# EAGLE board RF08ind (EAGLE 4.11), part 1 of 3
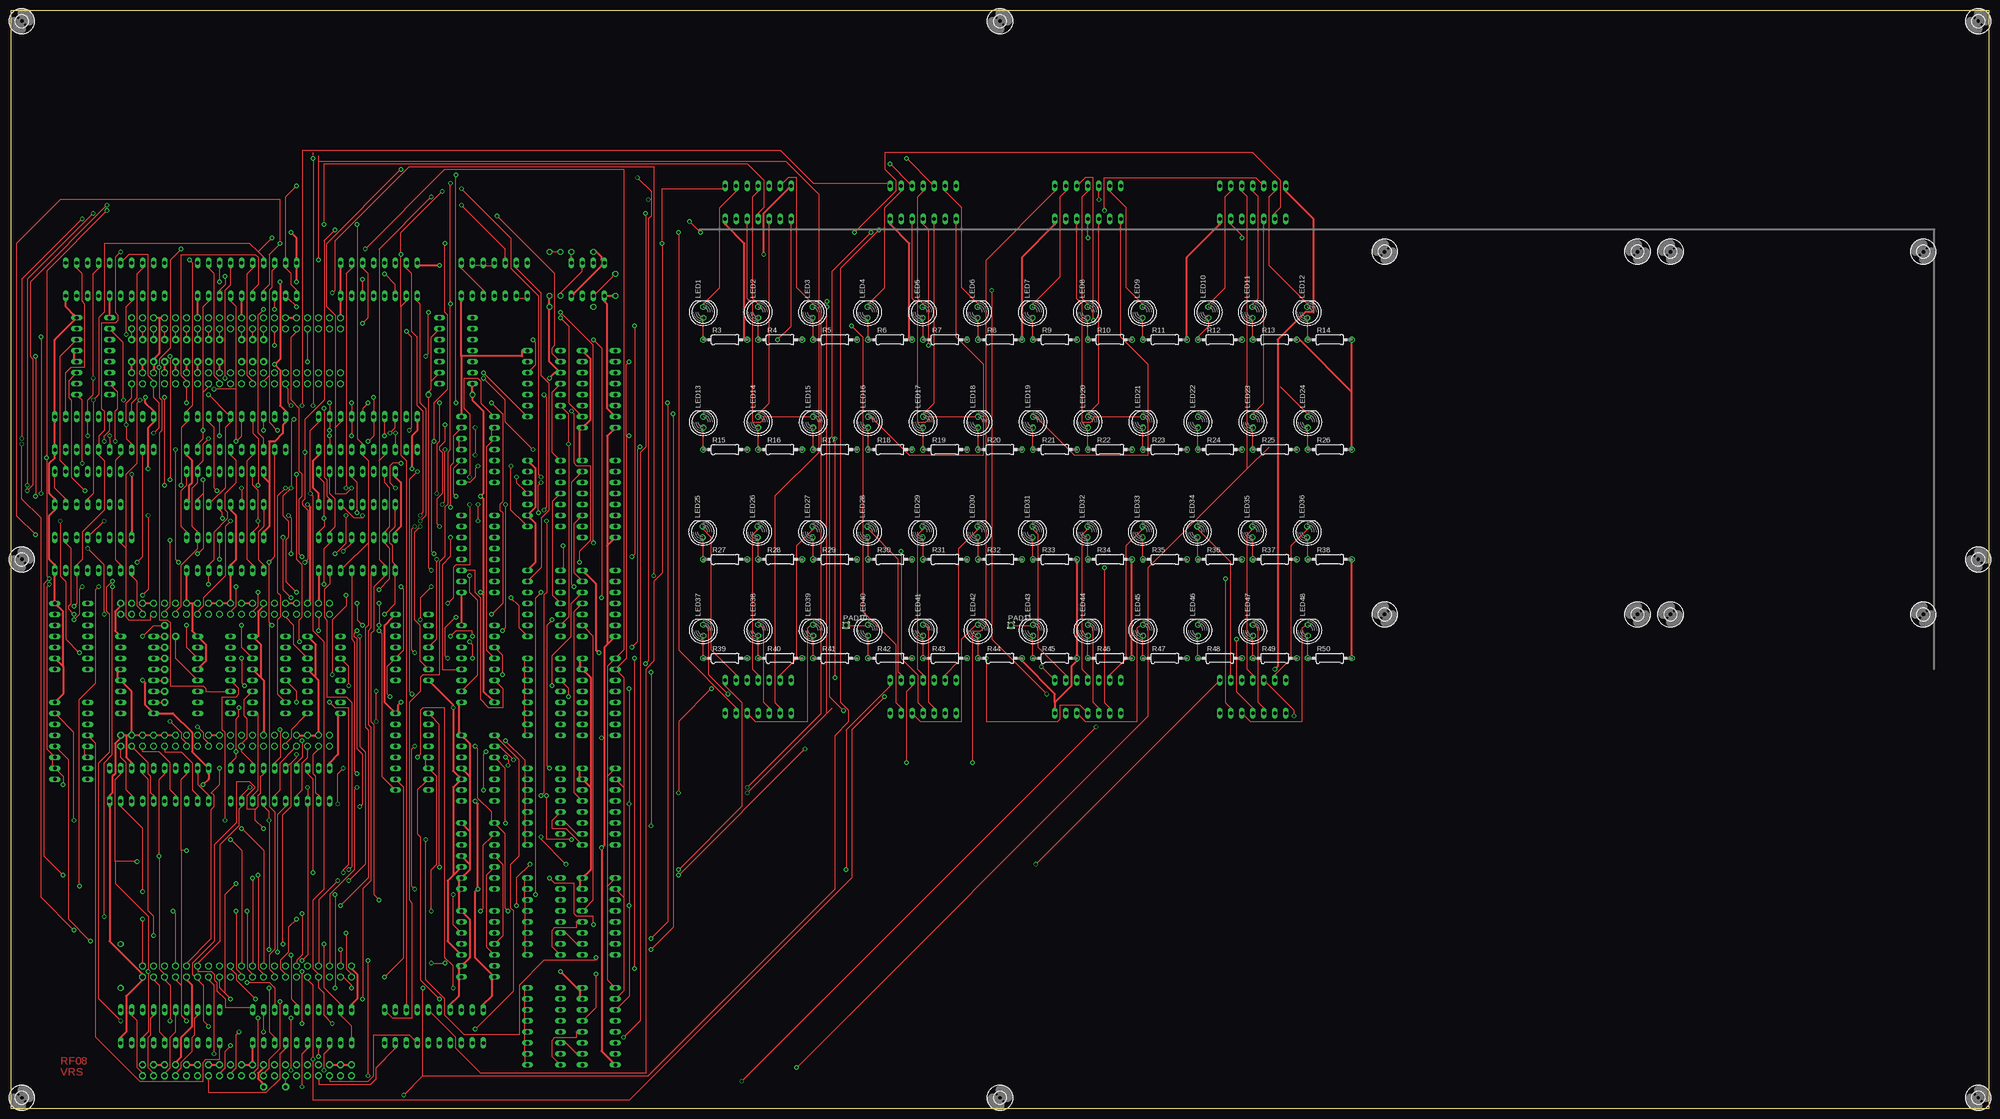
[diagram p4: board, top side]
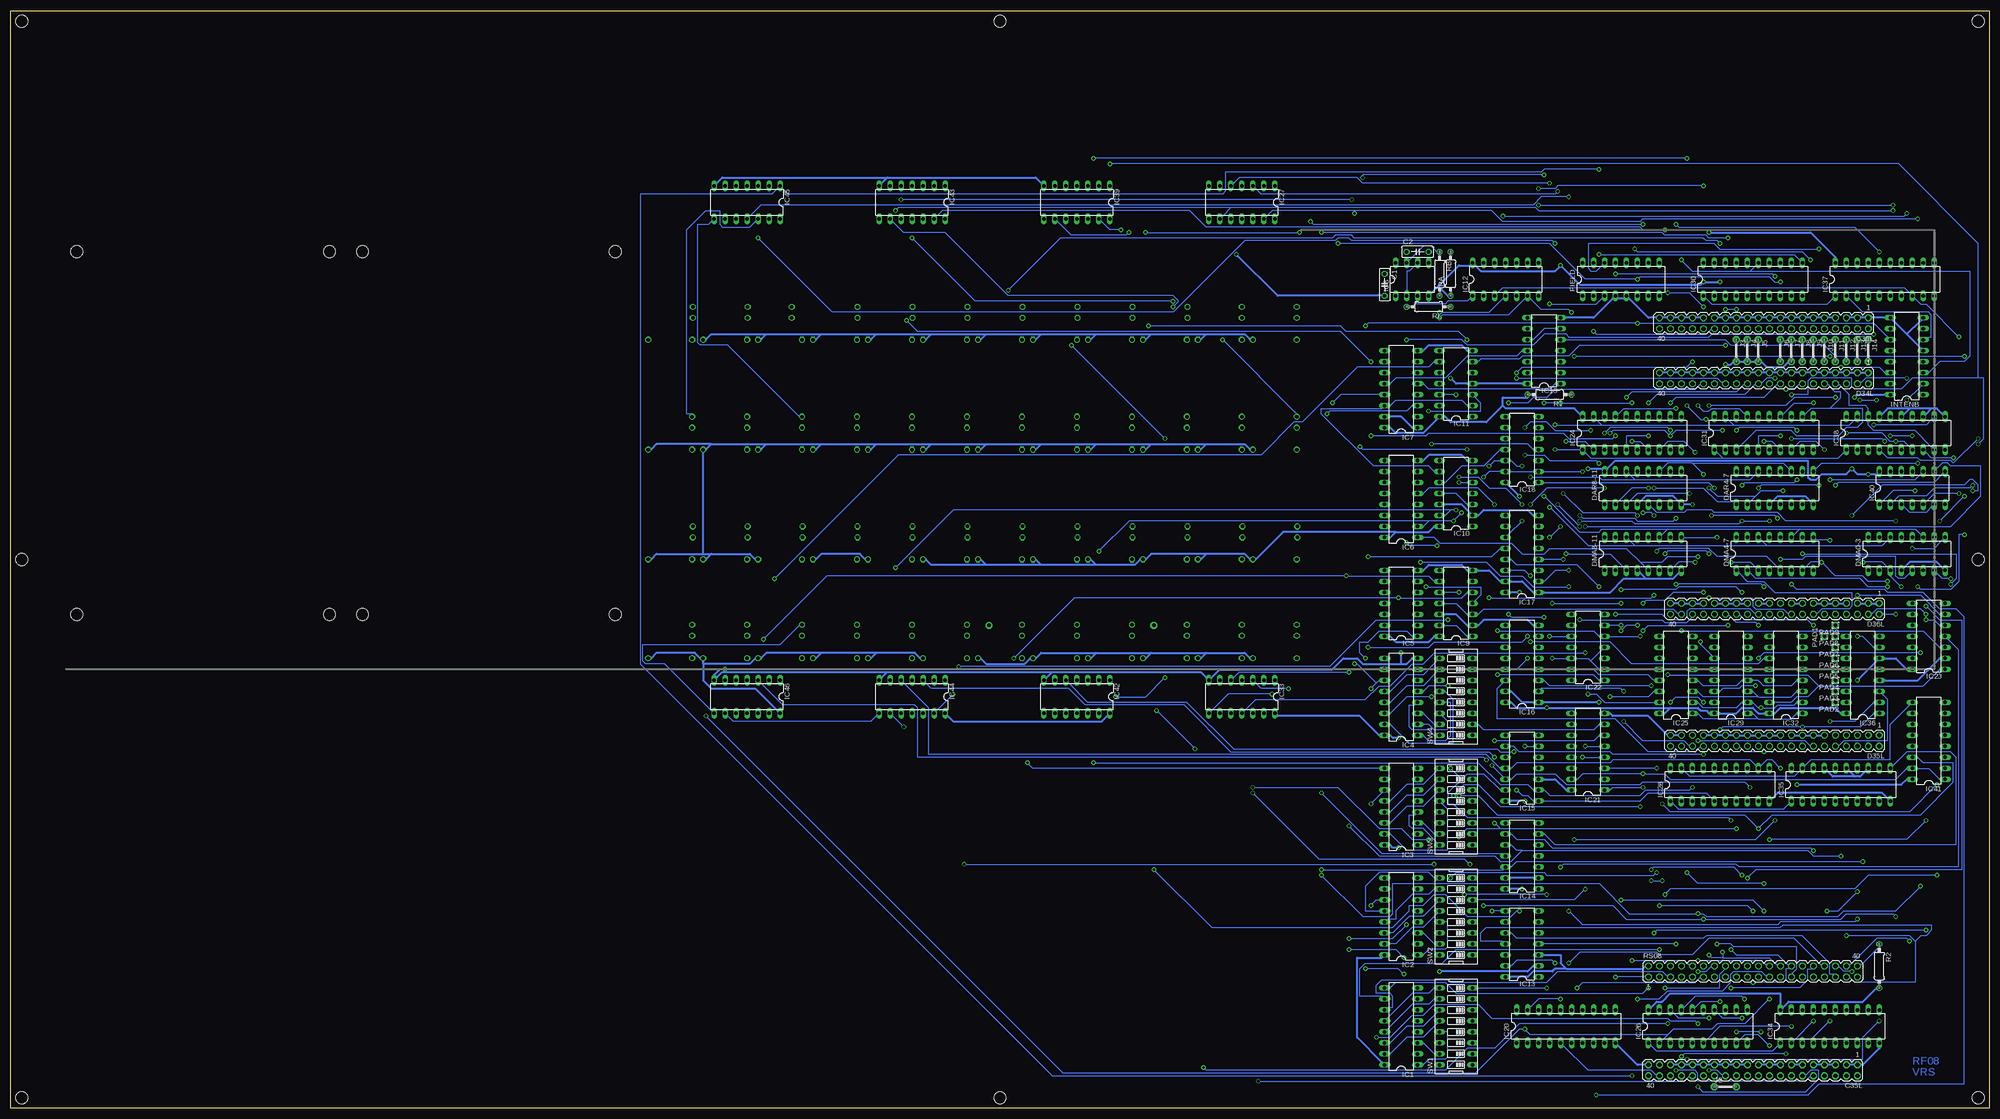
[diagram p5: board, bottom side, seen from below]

Size 457.18 x 253.67 mm. Coordinates in mm from the lower left corner, seen from the top.
Outline: 0,0 457.18,0 457.18,253.67 0,253.67 0,0
Copper layers (1*16): Top 0.035mm / dielectric 1.5mm / Bottom 0.035mm
Design rules "default": minimum track width 10mil, minimum drill 24mil, track to track 8mil, track to pad 8mil, pad to pad 8mil, via to via 8mil, smd to smd 8mil, copper to edge 40mil, drill to drill 8mil, minimum pad ring 10mil, minimum via ring 8mil, stop-mask expansion 4mil, vias tented up to drill 0mil, thermal gap 10mil
Net classes: 1 Power: width 0.508 mm

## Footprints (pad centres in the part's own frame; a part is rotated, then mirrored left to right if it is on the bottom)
C050-025X075 = drill 0.813 octagon: 1 -2.54,0; 2 2.54,0
MA20-2 = drill 1.016 octagon: 1 -24.13,-1.27; 2 -24.13,1.27; 3 -21.59,-1.27; 4 -21.59,1.27; 5 -19.05,-1.27; 6 -19.05,1.27; 7 -16.51,-1.27; 8 -16.51,1.27; 9 -13.97,-1.27; 10 -13.97,1.27; 11 -11.43,-1.27; 12 -11.43,1.27; 13 -8.89,-1.27; 14 -8.89,1.27; 15 -6.35,-1.27; 16 -6.35,1.27; 17 -3.81,-1.27; 18 -3.81,1.27; 19 -1.27,-1.27; 20 -1.27,1.27; 21 1.27,-1.27; 22 1.27,1.27; 23 3.81,-1.27; 24 3.81,1.27; 25 6.35,-1.27; 26 6.35,1.27; 27 8.89,-1.27; 28 8.89,1.27; 29 11.43,-1.27; 30 11.43,1.27; 31 13.97,-1.27; 32 13.97,1.27; 33 16.51,-1.27; 34 16.51,1.27; 35 19.05,-1.27; 36 19.05,1.27; 37 21.59,-1.27; 38 21.59,1.27; 39 24.13,-1.27; 40 24.13,1.27
DIL16 = drill 0.813 long: 1 -8.89,-3.81; 2 -6.35,-3.81; 3 -3.81,-3.81; 4 -1.27,-3.81; 5 1.27,-3.81; 6 3.81,-3.81; 7 6.35,-3.81; 8 8.89,-3.81; 9 8.89,3.81; 10 6.35,3.81; 11 3.81,3.81; 12 1.27,3.81; 13 -1.27,3.81; 14 -3.81,3.81; 15 -6.35,3.81; 16 -8.89,3.81
DIL14 = drill 0.813 long: 1 -7.62,-3.81; 2 -5.08,-3.81; 3 -2.54,-3.81; 4 0,-3.81; 5 2.54,-3.81; 6 5.08,-3.81; 7 7.62,-3.81; 8 7.62,3.81; 9 5.08,3.81; 10 2.54,3.81; 11 0,3.81; 12 -2.54,3.81; 13 -5.08,3.81; 14 -7.62,3.81
DIL08 = drill 0.813 long: 1 -3.81,-3.81; 2 -1.27,-3.81; 3 1.27,-3.81; 4 3.81,-3.81; 5 3.81,3.81; 6 1.27,3.81; 7 -1.27,3.81; 8 -3.81,3.81
DIL20 = drill 0.813 long: 1 -11.43,-3.81; 2 -8.89,-3.81; 3 -6.35,-3.81; 4 -3.81,-3.81; 5 -1.27,-3.81; 6 1.27,-3.81; 7 3.81,-3.81; 8 6.35,-3.81; 9 8.89,-3.81; 10 11.43,-3.81; 11 11.43,3.81; 12 8.89,3.81; 13 6.35,3.81; 14 3.81,3.81; 15 1.27,3.81; 16 -1.27,3.81; 17 -3.81,3.81; 18 -6.35,3.81; 19 -8.89,3.81; 20 -11.43,3.81
05 = drill 0.813 pad 1.6 octagon: 1 -2.54,0; 2 2.54,0
LED5MM = drill 0.813 octagon: A -1.27,0; K 1.27,0
1,6/0,8 = drill 0.813 pad 1.6 octagon: 1 0,0
0207/10 = drill 0.813 octagon: 1 -5.08,0; 2 5.08,0
EDG-08 = drill 0.813 long: 1 -8.89,-3.81; 2 -6.35,-3.81; 3 -3.81,-3.81; 4 -1.27,-3.81; 5 1.27,-3.81; 6 3.81,-3.81; 7 6.35,-3.81; 8 8.89,-3.81; 9 8.89,3.81; 10 6.35,3.81; 11 3.81,3.81; 12 1.27,3.81; 13 -1.27,3.81; 14 -3.81,3.81; 15 -6.35,3.81; 16 -8.89,3.81
2,8 = hole 2.8: 0,0

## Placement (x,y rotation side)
C1  .1uf  [C050-025X075]  139.69,190.34 270 bottom
C2  .1uf  [C050-025X075]  132.08,197.96 0 bottom
C35L  [MA20-2]  54.6,8.73 180 bottom
C36L  [MA20-2]  52.06,181.45 180 bottom
D34L  [MA20-2]  52.06,168.75 180 bottom
D35L  [MA20-2]  49.52,84.92 180 bottom
D36L  [MA20-2]  49.52,115.4 180 bottom
DAR4-7  74LS193N  [DIL16]  49.52,143.34 0 bottom
DAR8-11  74LS193N  [DIL16]  80.01,143.34 0 bottom
DMA0-3  74LS193N  [DIL16]  19.05,128.11 0 bottom
DMA4-7  74LS193N  [DIL16]  49.52,128.11 0 bottom
DMA8-11  74LS193N  [DIL16]  80.01,128.11 0 bottom
FIELD  74LS193N  [DIL16]  85.09,191.61 0 bottom
IC1  74LS151N  [DIL16]  135.88,18.89 90 bottom
IC2  74LS151N  [DIL16]  135.88,44.29 90 bottom
IC3  74LS151N  [DIL16]  135.88,69.68 90 bottom
IC4  74LS151N  [DIL16]  135.88,95.08 90 bottom
IC5  74LS20N  [DIL14]  135.88,116.67 90 bottom
IC6  74S139N  [DIL16]  135.88,140.81 90 bottom
IC7  74LS139N  [DIL16]  135.88,166.21 90 bottom
IC8  LM555N  [DIL08]  133.34,191.61 0 bottom
IC9  74S74N  [DIL14]  123.19,116.67 90 bottom
IC10  74S74N  [DIL14]  123.19,142.08 90 bottom
IC11  74S74N  [DIL14]  123.19,167.47 90 bottom
IC12  74LS00N  [DIL14]  111.76,191.61 0 bottom
IC13  74180N  [DIL14]  107.95,37.94 90 bottom
IC14  74180N  [DIL14]  107.95,58.26 90 bottom
IC15  74180N  [DIL14]  107.95,78.57 90 bottom
IC16  74S139N  [DIL16]  107.95,102.7 90 bottom
IC17  74S139N  [DIL16]  107.95,128.11 90 bottom
IC18  74LS00N  [DIL14]  107.95,152.24 90 bottom
IC19  7407N  [DIL14]  102.87,175.09 90 bottom
IC20  74S240N  [DIL20]  97.79,18.89 0 bottom
IC21  74LS139N  [DIL16]  92.7,82.38 90 bottom
IC22  7407N  [DIL14]  92.7,106.52 90 bottom
IC23  74S74N  [DIL14]  13.96,109.05 90 bottom
IC24  74S240N  [DIL20]  82.55,156.05 0 bottom
IC25  74S138N  [DIL16]  72.39,100.16 90 bottom
IC26  74S240N  [DIL20]  67.31,18.89 0 bottom
IC27  7404N  [DIL14]  172.72,209.39 180 bottom
IC28  74LS244N  [DIL20]  62.22,74.77 0 bottom
IC29  74S138N  [DIL16]  59.68,100.16 90 bottom
IC30  74S240N  [DIL20]  54.6,191.61 0 bottom
IC31  74S240N  [DIL20]  52.06,156.05 0 bottom
IC32  74S138N  [DIL16]  46.98,100.16 90 bottom
IC33  7404N  [DIL14]  172.72,95.08 180 bottom
IC34  74S240N  [DIL20]  36.82,18.89 0 bottom
IC35  74LS244N  [DIL20]  34.28,74.77 0 bottom
IC36  74S138N  [DIL16]  29.21,100.16 90 bottom
IC37  74S240N  [DIL20]  24.12,191.61 0 bottom
IC38  74S240N  [DIL20]  21.59,156.05 0 bottom
IC39  7404N  [DIL14]  210.81,209.39 180 bottom
IC40  74S03N  [DIL14]  17.78,143.34 0 bottom
IC41  74LS139N  [DIL16]  13.96,84.92 90 bottom
IC42  7404N  [DIL14]  210.81,95.08 180 bottom
IC43  7404N  [DIL14]  248.91,209.39 180 bottom
IC44  7404N  [DIL14]  248.91,95.08 180 bottom
IC45  7404N  [DIL14]  287.01,209.39 180 bottom
IC46  7404N  [DIL14]  287.01,95.08 180 bottom
INTENB  74LS193N  [DIL16]  19.05,173.83 90 bottom
J2  J5MM  [05]  60.95,4.92 0 bottom
J3  J5MM  [05]  58.41,175.09 270 bottom
J4  J5MM  [05]  55.88,175.09 270 bottom
J5  J5MM  [05]  53.34,175.09 270 bottom
J6  J5MM  [05]  48.25,175.09 270 bottom
J7  J5MM  [05]  45.71,175.09 270 bottom
J8  J5MM  [05]  43.17,175.09 270 bottom
J9  J5MM  [05]  40.63,175.09 270 bottom
J10  J5MM  [05]  38.09,175.09 270 bottom
J11  J5MM  [05]  35.55,175.09 270 bottom
J12  J5MM  [05]  33.02,175.09 270 bottom
J13  J5MM  [05]  30.48,175.09 270 bottom
J14  J5MM  [05]  27.94,175.09 270 bottom
LED1  [LED5MM]  160.02,183.99 90 top
LED2  [LED5MM]  172.72,183.99 90 top
LED3  [LED5MM]  185.29,183.99 90 top
LED4  [LED5MM]  197.99,183.99 90 top
LED5  [LED5MM]  210.69,183.99 90 top
LED6  [LED5MM]  223.39,183.99 90 top
LED7  [LED5MM]  236.09,183.99 90 top
LED8  [LED5MM]  248.79,183.99 90 top
LED9  [LED5MM]  261.49,183.99 90 top
LED10  [LED5MM]  276.73,183.99 90 top
LED11  [LED5MM]  286.89,183.99 90 top
LED12  [LED5MM]  299.59,183.99 90 top
LED13  [LED5MM]  160.02,158.59 90 top
LED14  [LED5MM]  172.72,158.59 90 top
LED15  [LED5MM]  185.41,158.59 90 top
LED16  [LED5MM]  198.12,158.59 90 top
LED17  [LED5MM]  210.81,158.59 90 top
LED18  [LED5MM]  223.52,158.59 90 top
LED19  [LED5MM]  236.22,158.59 90 top
LED20  [LED5MM]  248.91,158.59 90 top
LED21  [LED5MM]  261.62,158.59 90 top
LED22  [LED5MM]  274.31,158.59 90 top
LED23  [LED5MM]  287.01,158.59 90 top
LED24  [LED5MM]  299.72,158.59 90 top
LED25  [LED5MM]  159.89,133.19 90 top
LED26  [LED5MM]  172.59,133.19 90 top
LED27  [LED5MM]  185.29,133.19 90 top
LED28  [LED5MM]  197.99,133.19 90 top
LED29  [LED5MM]  210.69,133.19 90 top
LED30  [LED5MM]  223.39,133.19 90 top
LED31  [LED5MM]  236.09,133.19 90 top
LED32  [LED5MM]  248.79,133.19 90 top
LED33  [LED5MM]  261.49,133.19 90 top
LED34  [LED5MM]  274.19,133.19 90 top
LED35  [LED5MM]  286.89,133.19 90 top
LED36  [LED5MM]  299.59,133.19 90 top
LED37  [LED5MM]  160.02,110.45 90 top
LED38  [LED5MM]  172.72,110.45 90 top
LED39  [LED5MM]  185.41,110.45 90 top
LED40  [LED5MM]  198.12,110.45 90 top
LED41  [LED5MM]  210.81,110.45 90 top
LED42  [LED5MM]  223.52,110.45 90 top
LED43  [LED5MM]  236.22,110.45 90 top
LED44  [LED5MM]  248.91,110.45 90 top
LED45  [LED5MM]  261.62,110.45 90 top
LED46  [LED5MM]  274.31,110.45 90 top
LED47  [LED5MM]  287.01,110.45 90 top
LED48  [LED5MM]  299.72,110.45 90 top
PAD1  [1,6/0,8]  38.09,109.05 180 bottom
PAD2  [1,6/0,8]  35.55,93.81 180 bottom
PAD3  [1,6/0,8]  35.55,96.35 180 bottom
PAD4  [1,6/0,8]  35.55,98.89 180 bottom
PAD5  [1,6/0,8]  35.55,101.43 180 bottom
PAD6  [1,6/0,8]  35.55,103.97 180 bottom
PAD7  [1,6/0,8]  35.55,106.52 180 bottom
PAD8  [1,6/0,8]  35.55,109.05 180 bottom
PAD9  [1,6/0,8]  35.55,111.59 180 bottom
PAD10  [1,6/0,8]  193.03,111.59 0 top
PAD11  [1,6/0,8]  231.13,111.59 0 top
R1  5.1K  [0207/10]  101.59,164.94 180 bottom
R2  5.1K  [0207/10]  25.39,32.86 270 bottom
R3  330  [0207/10]  165.09,177.64 0 top
R4  330  [0207/10]  177.8,177.64 0 top
R5  330  [0207/10]  190.5,177.64 0 top
R6  330  [0207/10]  203.19,177.64 0 top
R7  330  [0207/10]  215.9,177.64 0 top
R8  330  [0207/10]  228.59,177.64 0 top
R9  330  [0207/10]  241.3,177.64 0 top
R10  330  [0207/10]  254,177.64 0 top
R11  330  [0207/10]  266.69,177.64 0 top
R12  330  [0207/10]  279.39,177.64 0 top
R13  330  [0207/10]  292.1,177.64 0 top
R14  330  [0207/10]  304.8,177.64 0 top
R15  330  [0207/10]  165.09,152.24 0 top
R16  330  [0207/10]  177.8,152.24 0 top
R17  330  [0207/10]  190.5,152.24 0 top
R18  330  [0207/10]  203.19,152.24 0 top
R19  330  [0207/10]  215.9,152.24 0 top
R20  330  [0207/10]  228.59,152.24 0 top
R21  330  [0207/10]  241.3,152.24 0 top
R22  330  [0207/10]  254,152.24 0 top
R23  330  [0207/10]  266.69,152.24 0 top
R24  330  [0207/10]  279.39,152.24 0 top
R25  330  [0207/10]  292.1,152.24 0 top
R26  330  [0207/10]  304.8,152.24 0 top
R27  330  [0207/10]  165.09,126.83 0 top
R28  330  [0207/10]  177.8,126.83 0 top
R29  330  [0207/10]  190.5,126.83 0 top
R30  330  [0207/10]  203.19,126.83 0 top
R31  330  [0207/10]  215.9,126.83 0 top
R32  330  [0207/10]  228.59,126.83 0 top
R33  330  [0207/10]  241.3,126.83 0 top
R34  330  [0207/10]  254,126.83 0 top
R35  330  [0207/10]  266.69,126.83 0 top
R36  330  [0207/10]  279.39,126.83 0 top
R37  330  [0207/10]  292.1,126.83 0 top
R38  330  [0207/10]  304.8,126.83 0 top
R39  330  [0207/10]  165.09,103.97 0 top
R40  330  [0207/10]  177.8,103.97 0 top
R41  330  [0207/10]  190.5,103.97 0 top
R42  330  [0207/10]  203.19,103.97 0 top
R43  330  [0207/10]  215.9,103.97 0 top
R44  330  [0207/10]  228.59,103.97 0 top
R45  330  [0207/10]  241.3,103.97 0 top
R46  330  [0207/10]  254,103.97 0 top
R47  330  [0207/10]  266.69,103.97 0 top
R48  330  [0207/10]  279.39,103.97 0 top
R49  330  [0207/10]  292.1,103.97 0 top
R50  330  [0207/10]  304.8,103.97 0 top
RA  470K  [0207/10]  124.45,192.88 90 bottom
RB  1.5K  [0207/10]  127,192.88 270 bottom
RL  1K  [0207/10]  129.53,185.25 180 bottom
RS08  [MA20-2]  54.6,31.59 0 bottom
SW1  [EDG-08]  123.19,18.89 90 bottom
SW2  [EDG-08]  123.19,44.29 90 bottom
SW3  [EDG-08]  123.19,69.68 90 bottom
SW4  [EDG-08]  123.19,95.08 90 bottom
U$1  [2,8]  2.54,126.83 0 top
U$2  [2,8]  228.59,251.3 0 top
U$3  [2,8]  2.54,2.38 0 top
U$4  [2,8]  228.59,2.38 0 top
U$5  [2,8]  2.54,251.3 0 top
U$6  [2,8]  454.66,2.38 0 top
U$7  [2,8]  454.66,126.83 0 top
U$8  [2,8]  454.66,251.3 0 top
U$9  [2,8]  317.5,197.96 90 top
U$10  [2,8]  317.5,114.13 90 top
U$11  [2,8]  375.92,197.96 90 top
U$12  [2,8]  375.92,114.13 90 top
U$13  [2,8]  383.54,197.96 90 top
U$14  [2,8]  383.54,114.13 90 top
U$15  [2,8]  441.95,197.96 90 top
U$16  [2,8]  441.95,114.13 90 top

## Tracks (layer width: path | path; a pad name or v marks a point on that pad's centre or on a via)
3CYC\
  Top 0.254: C35L.28 63.49,6.82 63.49,5.55 J2.1
601\  (via drill 0.61)
  Top 0.254: IC18.4 103.5,152.87 103.5,154.14 IC18.5 | IC11.13 127.63,161.76 128.9,160.49 v128.9,153.5 128.9,113.5 127.63,112.23 IC9.13 | v74.29,100.16 74.29,112.86 77.47,116.04 v77.47,118.58 | v115.56,117.94 117.47,116.04 117.47,110.96 118.74,109.69 IC9.1
  Bottom 0.254: 39.36,97.62 15.23,97.62 11.42,101.43 IC23.1 | 39.36,97.62 41.9,95.08 44.45,95.08 45.71,93.81 49.52,93.81 IC32.15 | IC9.1 120.65,109.05 123.19,111.59 125.73,111.59 IC9.13 | v128.9,153.5 106.68,153.5 105.41,152.24 IC18.4 | 39.36,97.62 41.9,100.16 v74.29,100.16 | v77.47,118.58 78.1,117.94 v115.56,117.94
602\  (via drill 0.61)
  Top 0.254: v63.49,143.34 61.59,141.44 61.59,119.21 62.22,118.58 62.22,113.5 61.59,112.86 61.59,95.72 62.86,94.45 IC29.15 | v107.95,148.43 107.31,147.79 107.31,145.89 106.04,144.62 105.41,144.62 IC18.1 | v115.56,148.43 115.56,138.27 118.74,135.09 IC10.1
  Bottom 0.254: v63.49,143.34 64.77,144.62 102.87,144.62 IC18.1 | v107.95,148.43 109.22,148.43 110.48,149.7 IC18.12 113.03,149.7 114.3,149.7 v115.56,148.43
604\  (via drill 0.61)
  Top 0.254: v92.7,95.72 92.07,96.35 92.07,145.25 v93.98,147.16 | v116.84,145.89 116.84,144.62 118.74,142.71 IC10.4
  Bottom 0.254: v92.7,95.72 90.8,95.72 88.9,93.81 77.47,93.81 IC25.15 | v93.98,147.16 102.87,147.16 IC18.2 105.41,147.16 110.48,147.16 IC18.13 113.03,147.16 115.56,147.16 v116.84,145.89
611\  (via drill 0.61)
  Top 0.254: IC32.14 49.52,96.35 45.08,96.35 45.08,96.99 44.45,97.62 36.82,97.62 36.82,112.23 36.19,112.86 34.28,112.86 34.28,156.05 34.92,156.68 34.92,163.67 34.28,164.3 v34.28,171.28 34.28,173.19 36.82,175.73 36.82,196.05 v39.36,198.59
  Bottom 0.254: v34.28,171.28 25.39,171.28 24.12,170.02 INTENB.14 | v39.36,198.59 62.22,198.59 63.49,199.86 92.7,199.86 92.7,194.15 92.07,193.51 90.8,193.51 89.53,194.78 FIELD.14
612\  (via drill 0.61)
  Top 0.254: v53.97,97.62 53.34,98.26 v53.34,103.97 | v15.87,105.24 12.69,108.42 12.69,121.75 11.42,123.02 v11.42,135.72 | v5.71,173.83 v5.71,141.44
  Bottom 0.254: v53.97,97.62 57.14,97.62 57.78,96.99 61.59,96.99 62.22,96.35 IC29.14 | v53.34,103.97 52.06,105.24 v15.87,105.24 | v5.71,141.44 v11.42,135.72 | v5.71,173.83 35.55,173.83 38.09,176.37 59.68,176.37 60.95,177.64 97.79,177.64 IC19.5
614\  (via drill 0.61)
  Top 0.254: v87.62,95.08 86.99,95.72 86.99,102.07 88.26,103.34 IC22.3 89.53,104.61 90.8,105.88 90.8,119.85 v90.17,120.48
  Bottom 0.254: v87.62,95.08 78.73,95.08 77.47,96.35 IC25.14 | v90.17,120.48 95.25,125.56 109.22,125.56 110.48,126.83 IC17.13
621\  (via drill 0.61)
  Top 0.254: v49.52,66.51 49.52,86.83 48.89,87.46 48.89,95.08 52.06,95.08 52.7,95.72 52.7,96.99 51.43,98.26 IC32.13 | v95.88,62.06 95.88,29.68 100.33,25.23 100.33,21.43 104.77,16.98 117.47,16.98 117.47,28.41 123.19,34.12 135.25,34.12 v135.25,34.76 | v147.95,36.66 153.03,41.74 v153.03,160.49
  Bottom 0.254: v49.52,66.51 53.97,62.06 v95.88,62.06 | v135.25,34.76 137.16,36.66 v147.95,36.66 | v153.03,160.49 152.4,161.12 134.62,161.12 133.34,162.4 IC7.3
622\  (via drill 0.61)
  Top 0.254: v66.04,93.81 66.04,96.35 64.13,98.26 IC29.13 | v73.66,93.81 74.93,92.54 78.1,92.54 78.1,56.35 76.83,55.08 v76.83,54.45 | v124.45,53.18 125.73,51.91 130.17,51.91 130.17,44.92 130.81,44.29 134.62,44.29 v134.62,42.38 | v147.95,39.2 151.76,43.02 v151.76,163.03
  Bottom 0.254: v66.04,93.81 67.31,95.08 72.39,95.08 v73.66,93.81 | v76.83,54.45 77.47,53.81 102.23,53.81 102.87,54.45 123.19,54.45 v124.45,53.18 | v134.62,42.38 137.79,39.2 v147.95,39.2 | v151.76,163.03 149.86,164.94 140.97,164.94 IC7.13
624\  (via drill 0.61)
  Top 0.254: v94.61,134.46 93.34,133.19 93.34,112.86 94.61,111.59 94.61,103.34 95.88,102.07 IC22.13 | v99.69,139.53 100.33,140.17 v100.33,152.24
  Bottom 0.254: IC25.13 77.47,98.89 78.73,100.16 90.17,100.16 91.44,101.43 95.25,101.43 IC22.13 | 61.59,150.33 34.92,150.33 33.65,151.6 IC38.1 | 61.59,150.33 62.86,151.6 IC31.1 | 61.59,150.33 92.07,150.33 93.34,151.6 IC24.1 94.61,152.24 v100.33,152.24 | v94.61,134.46 v99.69,139.53
641\  (via drill 0.61)
  Top 0.254: v106.04,107.78 106.68,107.15 v106.68,103.97
  Bottom 0.254: v106.04,107.78 87.62,107.78 82.55,102.7 53.34,102.7 52.06,103.97 IC32.11 | v106.68,103.97 109.22,101.43 110.48,101.43 IC16.13
642\  (via drill 0.61)
  Top 0.254: v66.67,107.78 66.67,112.86 67.31,113.5 67.31,125.56 66.04,126.83 v66.04,146.52
  Bottom 0.254: v66.67,107.78 66.67,107.15 64.13,104.61 IC29.11 | v66.04,146.52 68.58,149.06 | 68.58,149.06 74.29,149.06 75.56,147.79 DAR8-11.11 | 68.58,149.06 47.62,149.06 46.35,147.79 DAR4-7.11
644\  (via drill 0.61)
  Top 0.254: v78.1,97.62 78.1,102.07 76.83,103.34 IC25.11
  Bottom 0.254: v78.1,97.62 101.59,97.62 102.87,98.89 IC16.3
645\  (via drill 0.61)
  Top 0.254: v101.59,131.92 101.59,127.47 99.69,125.56 99.69,101.43 102.87,101.43 IC16.4 | v99.06,134.46 98.42,135.09 98.42,140.81 99.69,142.08 99.69,151.6 99.06,152.24 99.06,152.87 100.33,154.14 v100.33,157.95
  Bottom 0.254: 59.05,157.95 32.38,157.95 31.11,159.22 IC38.19 | 59.05,157.95 60.32,159.22 IC31.19 | 89.53,157.95 90.8,159.22 IC24.19 | 89.53,157.95 59.05,157.95 | v99.06,134.46 v101.59,131.92 | v100.33,157.95 89.53,157.95
ACB00\  (via drill 0.61)
  Top 0.254: IC38.3 27.94,153.5 26.67,154.78 v26.67,157.95 26.67,163.03 27.94,164.3 27.94,166.84 D34L.2 | IC38.12 12.69,161.12 12.69,170.02 13.96,171.28 17.14,171.28 17.14,185.89 16.51,186.53 16.51,192.88 15.23,194.15 IC37.12
  Bottom 0.254: v26.67,157.95 14.6,157.95 13.33,159.22 IC38.12
ACB01\  (via drill 0.61)
  Top 0.254: v22.86,155.41 22.86,153.5 IC38.5 | v17.78,155.41 17.78,158.59 IC38.14 17.78,161.12 17.78,163.67 19.05,164.94 v19.05,168.75 19.05,192.88 20.32,194.15 IC37.14
  Bottom 0.254: v17.78,155.41 v22.86,155.41 | v19.05,168.75 28.57,168.75 29.84,167.47 D34L.4
ACB02\  (via drill 0.61)
  Top 0.254: v21.59,154.14 21.59,155.41 22.86,156.68 22.86,158.59 IC38.16 | IC37.16 26.03,196.05 27.3,197.32 31.75,197.32 31.75,169.38 33.02,168.11 D34L.6 33.02,166.84 33.02,164.3 34.28,163.03 34.28,157.31 v33.02,156.05
  Bottom 0.254: IC38.7 18.41,152.87 19.68,154.14 v21.59,154.14 22.86,154.14 24.76,156.05 v33.02,156.05
ACB03\
  Top 0.254: IC37.18 30.48,194.15 29.21,192.88 29.21,164.3 27.94,163.03 27.94,161.12 IC38.18
  Bottom 0.254: IC38.9 13.33,152.87 17.14,156.68 26.67,156.68 27.94,157.95 27.94,158.59 IC38.18 27.94,161.12 27.94,161.76 28.57,162.4 32.38,162.4 32.38,164.94 34.92,167.47 D34L.8
ACB04\  (via drill 0.61)
  Top 0.254: v60.95,184.62 60.95,186.53 IC30.3 | v58.41,184.62 57.14,183.35 57.14,156.05 58.41,154.78 58.41,153.5 IC31.3
  Bottom 0.254: 36.82,161.76 41.27,161.76 42.54,160.49 IC31.12 | 36.82,161.76 34.28,164.3 34.28,165.57 35.55,165.57 37.46,167.47 D34L.10 | 36.82,161.76 29.21,161.76 29.21,158.59 30.48,157.31 33.02,157.31 34.92,155.41 44.45,155.41 45.71,156.68 53.97,156.68 57.78,152.87 IC31.3 | v58.41,184.62 v60.95,184.62
ACB05\  (via drill 0.61)
  Top 0.254: v40.63,163.03 40.63,166.84 D34L.12 40.63,168.11 39.36,169.38 39.36,197.32 56.51,197.32 57.14,196.69 57.14,190.34 55.88,189.06 IC30.5 | v48.25,155.41 48.25,158.59 IC31.14
  Bottom 0.254: v40.63,163.03 45.08,163.03 47.62,160.49 IC31.14 | v48.25,155.41 53.34,155.41 53.34,153.5 IC31.5
ACB06\  (via drill 0.61)
  Top 0.254: IC31.16 53.34,158.59 53.34,155.41 v52.06,154.14 52.06,166.21 | 52.06,166.21 52.06,185.25 50.79,186.53 IC30.7 | 52.06,166.21 v46.98,166.21
  Bottom 0.254: v52.06,154.14 50.16,154.14 48.89,152.87 IC31.7 | v46.98,166.21 45.08,166.21 43.81,167.47 D34L.14
ACB07\  (via drill 0.61)
  Top 0.254: 44.45,165.57 v44.45,156.68 44.45,154.78 43.17,153.5 IC31.9 | 44.45,165.57 45.71,166.84 D34L.16 | 44.45,165.57 44.45,185.25 45.71,186.53 IC30.9 | v58.41,156.68 58.41,158.59 IC31.18
  Bottom 0.254: v58.41,156.68 57.78,157.31 45.08,157.31 v44.45,156.68
ACB08\  (via drill 0.61)
  Top 0.254: IC30.12 45.71,194.15 46.98,192.88 46.98,169.38 48.25,168.11 D34L.18 | v73.66,163.03 73.66,161.12 IC24.12 73.66,158.59 v73.66,156.68 | v88.9,156.05 88.9,153.5 IC24.3
  Bottom 0.254: v73.66,163.03 72.39,164.3 52.06,164.3 48.89,167.47 D34L.18 | v88.9,156.05 87.62,157.31 74.29,157.31 v73.66,156.68
ACB09\  (via drill 0.61)
  Top 0.254: v78.73,155.41 78.73,158.59 IC24.14 78.73,161.12 v78.73,163.03 | v49.52,168.75 49.52,189.06 50.79,190.34 50.79,194.15 IC30.14
  Bottom 0.254: v78.73,155.41 83.81,155.41 83.81,153.5 IC24.5 | v49.52,168.75 51.43,168.75 52.7,167.47 D34L.22 53.97,167.47 56.51,164.94 76.83,164.94 v78.73,163.03
ACB10\  (via drill 0.61)
  Top 0.254: v82.55,154.14 83.81,155.41 83.81,158.59 IC24.16 83.81,161.12 v83.81,164.3 | IC30.16 55.88,194.15 54.6,192.88 54.6,169.38 55.88,168.11 D34L.24
  Bottom 0.254: v82.55,154.14 80.64,154.14 79.37,152.87 IC24.7 | v83.81,164.3 82.55,165.57 58.41,165.57 56.51,167.47 D34L.24
ACB11\  (via drill 0.61)
  Top 0.254: v73.66,155.41 73.66,153.5 IC24.9 | v87.62,156.05 88.9,157.31 88.9,158.59 IC24.18 | 59.68,169.38 59.68,189.06 60.32,189.7 60.32,193.51 60.95,194.15 IC30.18 | 59.68,169.38 58.41,168.11 D34L.26 | v61.59,156.68 59.68,158.59 59.68,169.38
  Bottom 0.254: v87.62,156.05 86.99,156.68 74.93,156.68 v73.66,155.41 72.39,156.68 v61.59,156.68
ACCLEAR\  (via drill 0.61)
  Top 0.254: v111.12,163.03 113.66,160.49 113.66,140.17 113.03,139.53 113.03,138.27 113.66,137.63 113.66,116.67 v111.12,114.13 | v102.87,113.5 100.33,110.96 100.33,104.61 v100.96,103.97
  Bottom 0.254: 92.07,103.34 92.7,103.97 95.25,103.97 IC22.12 97.79,103.97 v100.96,103.97 | 92.07,103.34 90.17,101.43 IC22.2 | 92.07,103.34 89.53,105.88 IC22.4 | v111.12,163.03 106.68,163.03 105.41,164.3 102.23,164.3 100.33,166.21 67.94,166.21 66.67,167.47 D34L.32 | v111.12,114.13 110.48,113.5 v102.87,113.5
BAC00  (via drill 0.61)
  Top 0.254: v17.78,129.38 21.59,125.56 v21.59,114.13
  Bottom 0.254: v17.78,129.38 12.69,129.38 10.79,131.28 DMA0-3.9 | v21.59,114.13 24.76,114.13 D36L.2
BAC01  (via drill 0.61)
  Top 0.254: v14.6,114.13 13.33,115.4 13.33,116.04 13.96,116.67 13.96,129.38 12.69,130.65 DMA0-3.10
  Bottom 0.254: v14.6,114.13 15.87,115.4 26.03,115.4 27.3,114.13 D36L.4
BAC02
  Top 0.254: DMA0-3.1 27.94,123.02 29.21,121.75 29.21,116.04 30.48,114.77 D36L.6
BAC03  (via drill 0.61)
  Top 0.254: 26.67,129.38 25.39,130.65 DMA0-3.15 | 26.67,129.38 26.67,113.5 27.3,112.86 32.38,112.86 32.38,114.13 D36L.8 | v26.03,163.67 26.03,177 23.49,179.54 INTENB.10 | v29.84,163.67 29.21,163.03 29.21,149.06 26.67,146.52 26.67,129.38
  Bottom 0.254: v29.84,163.67 v26.03,163.67
BAC04  (via drill 0.61)
  Top 0.254: DMA4-7.9 40.63,133.19 39.36,134.46 39.36,142.71 40.63,143.98 40.63,145.89 DAR4-7.9 | v16.51,149.06 16.51,163.67 15.87,164.3 INTENB.1 | v36.82,131.28 36.82,116.04 35.55,114.77 D36L.10
  Bottom 0.254: v16.51,149.06 38.73,149.06 40,147.79 DAR4-7.9 | v36.82,131.28 40,131.28 DMA4-7.9
BAC05  (via drill 0.61)
  Top 0.254: v24.12,154.14 24.12,161.12 24.76,161.76 24.76,165.57 23.49,166.84 INTENB.15 | v45.71,154.78 44.45,153.5 44.45,149.7 43.17,148.43 DAR4-7.10 43.17,145.89 43.17,144.62 41.9,143.34 41.9,134.46 43.17,133.19 DMA4-7.10 43.17,130.65 43.17,129.38 39.36,125.56 39.36,116.04 38.09,114.77 D36L.12
  Bottom 0.254: v24.12,154.14 24.76,154.78 v45.71,154.78
BAC06  (via drill 0.61)
  Top 0.254: DMA4-7.1 58.41,125.56 57.14,126.83 57.14,133.19 58.41,134.46 58.41,138.27 DAR4-7.1 | v77.47,143.34 77.47,192.88 78.73,194.15 FIELD.10
  Bottom 0.254: v77.47,143.34 66.04,143.34 62.86,140.17 59.05,140.17 DAR4-7.1 | D36L.14 40,114.13 38.73,115.4 32.38,115.4 31.75,116.04 31.75,119.21 49.52,119.21 52.06,121.75 55.88,121.75 57.78,123.66 DMA4-7.1
BAC07  (via drill 0.61)
  Top 0.254: DMA4-7.15 55.88,133.19 57.14,134.46 v57.14,135.72 57.14,142.71 55.88,143.98 55.88,145.89 DAR4-7.15 | v94.61,135.72 95.88,137 95.88,161.76 94.61,163.03 94.61,185.89 93.98,186.53 FIELD.1 | v50.79,135.72 49.52,134.46 49.52,123.02 44.45,117.94 44.45,116.04 43.17,114.77 D36L.16
  Bottom 0.254: v94.61,135.72 82.55,135.72 81.91,135.09 57.78,135.09 v57.14,135.72 v50.79,135.72
BAC08  (via drill 0.61)
  Top 0.254: DMA8-11.9 71.12,133.19 72.39,134.46 v72.39,136.36 72.39,144.62 71.12,145.89 DAR8-11.9 | v94.61,137 95.25,137.63 95.25,161.12 93.98,162.4 93.98,178.27 92.7,179.54 92.7,192.88 91.44,194.15 FIELD.15 | v64.77,117.94 62.86,119.85 v62.86,131.92
  Bottom 0.254: v94.61,137 93.98,136.36 81.91,136.36 81.28,135.72 73.02,135.72 v72.39,136.36 | v64.77,117.94 54.6,117.94 54.6,116.04 53.97,115.4 47.62,115.4 46.35,114.13 D36L.18 | v62.86,131.92 70.48,131.92 DMA8-11.9
BAC09  (via drill 0.61)
  Top 0.254: DAR8-11.10 73.66,145.89 73.66,142.08 74.93,140.81 74.93,134.46 73.66,133.19 DMA8-11.10 73.66,130.65 72.39,129.38 v72.39,121.12 | v52.06,120.48 52.06,116.04 50.79,114.77 D36L.22
  Bottom 0.254: v52.06,120.48 52.7,121.12 v72.39,121.12
BAC10  (via drill 0.61)
  Top 0.254: DAR8-11.1 88.9,138.27 88.9,134.46 87.62,133.19 87.62,130.65 88.26,130.01 88.26,126.2 88.9,125.56 DMA8-11.1 88.9,123.02 88.9,116.67 v86.36,114.13
  Bottom 0.254: v86.36,114.13 75.56,114.13 74.29,112.86 70.48,112.86 69.84,113.5 69.84,114.77 69.21,115.4 55.24,115.4 53.97,114.13 D36L.24
BAC11  (via drill 0.61)
  Top 0.254: DAR8-11.15 86.36,145.89 86.36,144.62 87.62,143.34 87.62,134.46 86.36,133.19 DMA8-11.15 86.36,130.65 87.62,129.38 87.62,122.39 v85.09,119.85 | v57.14,119.21 57.14,116.04 55.88,114.77 D36L.26
  Bottom 0.254: v57.14,119.21 58.41,120.48 71.75,120.48 72.39,119.85 v85.09,119.85
BADDAC\  (via drill 0.61)
  Top 0.254: v109.22,170.02 118.74,160.49 IC11.1 | v68.58,172.56 68.58,179.54 C36L.34
  Bottom 0.254: v109.22,170.02 107.95,171.28 69.84,171.28 v68.58,172.56
BBREAK\  (via drill 0.61)
  Top 0.254: v99.06,25.23 94.61,29.68 94.61,62.7 93.98,63.34 93.98,73.49 95.88,75.4 IC21.15 | v67.31,127.47 66.67,128.11 66.67,140.81 67.31,141.44 67.31,146.52 66.67,147.16 66.67,161.76 64.77,163.67 64.77,178.27 66.04,179.54 C36L.32 | v80.01,77.3 79.37,77.94 79.37,107.78 78.73,108.42 78.73,123.02 DMA8-11.5
  Bottom 0.254: IC41.1 11.42,76.03 13.96,78.57 16.51,78.57 IC41.15 19.05,78.57 21.59,76.03 73.66,76.03 74.93,77.3 v80.01,77.3 93.98,77.3 95.25,76.03 IC21.15 | v99.06,25.23 104.14,25.23 106.04,23.33 IC20.19 | 80.64,126.2 83.81,129.38 101.59,129.38 102.87,128.11 107.95,128.11 110.48,130.65 127,130.65 128.27,131.92 130.81,131.92 IC6.1 | 80.64,126.2 79.37,124.93 DMA8-11.5 | v67.31,127.47 74.29,127.47 75.56,126.2 80.64,126.2
BINIT  (via drill 0.61)
  Top 0.254: IC9.11 126.36,117.31 125.09,118.58 125.09,140.17 126.36,141.44 IC10.11 | v71.12,110.32 71.12,113.5 D36L.38
  Bottom 0.254: IC9.11 125.73,116.67 123.19,116.67 120.65,114.13 IC9.3 118.11,114.13 116.84,115.4 73.02,115.4 71.75,114.13 D36L.38 | IC10.3 120.65,139.53 123.19,142.08 125.73,142.08 IC10.11 | v71.12,110.32 15.23,110.32 11.42,106.52 IC23.3
BIOP1  (via drill 0.61)
  Top 0.254: v40.63,111.59 40.63,106.52 42.54,104.61 IC32.6
  Bottom 0.254: v40.63,111.59 41.9,112.86 56.51,112.86 57.78,114.13 D36L.28
BIOP2  (via drill 0.61)
  Top 0.254: v53.34,111.59 53.34,106.52 55.24,104.61 IC29.6
  Bottom 0.254: v53.34,111.59 53.97,112.23 58.41,112.23 60.32,114.13 D36L.30
BIOP4
  Top 0.254: IC25.6 67.94,104.61 65.4,107.15 65.4,111.59 63.49,113.5 D36L.32
BMB00
  Top 0.254: IC35.8 27.94,72.22 26.67,73.49 26.67,79.84 25.39,81.11 25.39,83.02 D35L.2
BMB01
  Top 0.254: IC35.6 33.02,72.22 32.38,72.86 32.38,76.67 31.75,77.3 31.75,79.84 28.57,83.02 28.57,83.65 D35L.4
BMB02
  Top 0.254: IC35.4 38.09,72.22 36.82,73.49 36.82,79.84 34.28,82.38 30.48,82.38 30.48,83.02 D35L.6
BMB03
  Top 0.254: IC35.2 43.17,72.22 41.9,73.49 41.9,79.84 39.36,82.38 35.55,82.38 35.55,83.02 D35L.10
  Bottom 0.254: IC36.3 24.76,95.72 23.49,94.45 23.49,84.92 33.65,84.92 34.92,83.65 D35L.10
BMB04  (via drill 0.61)
  Top 0.254: v36.82,89.37 39.36,86.83 39.36,85.56 40.63,84.29 D35L.14 | v67.31,84.92 67.31,81.11 66.04,79.84 IC28.17
  Bottom 0.254: v36.82,89.37 31.11,89.37 26.67,93.81 IC36.2 | v67.31,84.92 42.54,84.92 41.27,83.65 D35L.14
BMB05  (via drill 0.61)
  Top 0.254: v43.17,88.1 44.45,86.83 44.45,85.56 45.71,84.29 D35L.18 | v62.22,87.46 62.22,81.11 60.95,79.84 IC28.15
  Bottom 0.254: IC36.1 26.67,91.27 29.84,88.1 v43.17,88.1 61.59,88.1 v62.22,87.46
BMB06
  Top 0.254: IC28.13 55.88,79.84 53.34,82.38 53.34,83.02 D35L.24 53.34,84.29 54.6,85.56 54.6,90 53.97,90.64 53.97,94.45 55.24,95.72 IC29.3
  Bottom 0.254: 53.34,95.08 45.71,95.08 44.45,96.35 IC32.3 | 53.34,95.08 54.6,96.35 IC29.3 | 53.34,95.08 66.04,95.08 67.31,96.35 IC25.3
BMB07  (via drill 0.61)
  Top 0.254: IC28.11 50.79,79.84 52.06,81.11 v52.06,82.38 52.06,90 52.7,90.64 v52.7,92.54
  Bottom 0.254: v52.06,82.38 56.51,82.38 57.78,83.65 D35L.28 | IC32.2 44.45,93.81 45.08,93.18 48.89,93.18 49.52,92.54 v52.7,92.54 53.34,92.54 54.6,93.81 IC29.2 57.14,93.81 58.41,92.54 66.04,92.54 67.31,93.81 IC25.2
BMB08
  Top 0.254: IC28.8 55.88,72.22 57.14,73.49 57.14,91.27 IC29.1 | D35L.32 63.49,84.29 64.77,85.56 64.77,87.46 67.94,90.64 IC25.1
  Bottom 0.254: 53.34,90 45.71,90 44.45,91.27 IC32.1 | 53.34,90 54.6,91.27 IC29.1 | 53.34,90 66.04,90 67.31,91.27 IC25.1
BMB09
  Top 0.254: IC28.6 60.95,72.22 62.22,73.49 62.22,79.84 65.4,83.02 65.4,83.65 D35L.34 | IC17.3 105.41,124.29 107.31,124.29 107.31,119.21 108.58,117.94 108.58,94.45 110.48,92.54 113.66,92.54 113.66,96.99 112.39,98.26 IC16.14
  Bottom 0.254: IC16.14 112.39,98.26 113.66,96.99 113.66,90 86.36,90 78.73,82.38 67.94,82.38 66.67,83.65 D35L.34
BMB10  (via drill 0.61)
  Top 0.254: IC28.4 66.04,72.22 67.31,73.49 67.31,79.84 68.58,81.11 68.58,83.02 D35L.36 | v106.04,123.02 106.04,119.21 107.95,117.31 107.95,100.16 104.77,96.99 IC16.2 | v84.45,89.37 v84.45,96.35
  Bottom 0.254: v106.04,123.02 107.31,124.29 110.48,124.29 IC17.14 | v84.45,89.37 80.01,84.92 70.48,84.92 69.21,83.65 D35L.36 | v84.45,96.35 85.09,96.99 103.5,96.99 IC16.2
BMB11
  Top 0.254: IC28.2 71.12,72.22 70.48,72.86 70.48,76.67 69.84,77.3 69.84,81.75 71.12,83.02 D35L.38
BRK_RQ  (via drill 0.61)
  Top 0.254: v120.65,177.64 121.28,177 121.28,171.92 120.01,170.65 IC11.5 | v194.31,180.81 196.84,178.27 196.84,114.77 204.47,107.15 204.47,93.81 205.74,92.54 IC42.13
  Bottom 0.254: v120.65,177.64 122.55,179.54 148.59,179.54 149.86,180.81 v194.31,180.81
BRK_RQ\  (via drill 0.61)
  Top 0.254: v60.95,176.37 60.95,179.54 C36L.28
  Bottom 0.254: v60.95,176.37 94.61,176.37 97.15,173.83 107.95,173.83 108.58,173.19 117.47,173.19 118.11,172.56 IC11.6
BTS1  (via drill 0.61)
  Top 0.254: v129.53,161.12 130.17,160.49 130.17,149.06 130.81,148.43 133.98,148.43 133.98,131.28 131.44,128.74 v131.44,126.2 | v97.15,120.48 94.61,117.94 v94.61,112.86
  Bottom 0.254: v129.53,161.12 117.47,161.12 117.47,163.03 118.74,164.3 IC11.3 | v131.44,126.2 116.2,126.2 113.03,123.02 107.95,123.02 105.41,120.48 v97.15,120.48 | v94.61,112.86 75.56,112.86 74.93,112.23 69.84,112.23 68.58,113.5 D36L.36
BUSY
  Bottom 0.254: IC10.9 128.27,147.16 129.53,148.43 142.24,148.43 154.3,160.49 154.3,161.76 140.33,161.76 IC7.14 138.43,162.4 137.16,163.67 121.92,163.67 120.65,162.4 IC11.2
BWCO
  Bottom 0.254: IC44.8 257.17,90.64 258.44,89.37 290.19,89.37 291.46,90.64 IC46.9
BWCO\  (via drill 0.61)
  Top 0.254: v123.19,138.27 123.82,138.9 123.82,164.3 v123.19,164.94 | v252.72,124.93 252.72,93.81 254,92.54 IC44.9 | v250.82,88.1 v168.91,6.18
  Bottom 0.254: 124.45,138.27 125.73,137 IC10.13 | v123.19,138.27 124.45,138.27 | v123.19,164.94 125.73,164.94 IC11.12 | v252.72,124.93 239.39,138.27 124.45,138.27 | v168.91,6.18 70.48,6.18 69.21,7.46 C35L.32 | v250.82,88.1 253.36,90.64 IC44.9
CIE  (via drill 0.61)
  Top 0.254: v71.12,196.05 71.12,218.91 | 71.12,218.91 71.12,220.18 | IC33.9 177.8,92.54 176.53,93.81 176.53,141.44 186.69,151.6 186.69,211.29 179.06,218.91 71.12,218.91 | v17.14,142.71 13.96,145.89 13.96,163.67 13.33,164.3 13.33,168.11 14.6,169.38 INTENB.3
  Bottom 0.254: v71.12,196.05 68.58,193.51 55.24,193.51 | 55.24,193.51 53.97,194.78 IC30.15 | 55.24,193.51 4.44,193.51 4.44,173.83 5.71,172.56 11.42,172.56 13.96,170.02 INTENB.3 | v17.14,142.71 22.22,142.71 24.76,140.17 IC40.1
DA00\
  Top 0.254: C36L.2 27.94,179.54 27.94,178.27 J14.1
DA01\
  Top 0.254: C36L.4 30.48,179.54 30.48,178.27 J13.1
DA02\
  Top 0.254: C36L.6 33.02,179.54 33.02,178.27 J12.1
DA03\
  Top 0.254: C36L.8 35.55,179.54 35.55,178.27 J11.1
DA04\
  Top 0.254: C36L.10 38.09,179.54 38.09,178.27 J10.1
DA05\
  Top 0.254: C36L.12 40.63,179.54 40.63,178.27 J9.1
DA06\
  Top 0.254: C36L.14 43.17,179.54 43.17,178.27 J8.1
DA07\
  Top 0.254: C36L.16 45.71,179.54 45.71,178.27 J7.1
DA08\
  Top 0.254: C36L.18 48.25,179.54 48.25,178.27 J6.1
DA09\
  Top 0.254: C36L.22 53.34,179.54 53.34,178.27 J5.1
DA10\
  Top 0.254: C36L.24 55.88,179.54 55.88,178.27 J4.1
DA11\
  Top 0.254: C36L.26 58.41,179.54 58.41,178.27 J3.1
DAR04  (via drill 0.61)
  Top 0.254: v76.83,78.57 75.56,77.3 v75.56,70.32 | v12.06,74.77 12.06,76.67 10.79,77.94 IC41.2 9.52,79.21 9.52,80.48 IC41.3 9.52,81.75 8.25,83.02 8.25,120.48 v8.88,121.12 | 44.45,142.08 43.17,140.81 DAR4-7.7 | v44.45,145.25 44.45,142.08 | v57.14,143.98 57.14,154.78 55.88,156.05 55.88,158.59 IC31.17 | v67.31,162.4 67.31,221.45 177.8,221.45 185.41,213.83 202.56,213.83 IC39.1 | v43.17,128.11 44.45,129.38 44.45,142.08
  Bottom 0.254: v76.83,78.57 87.62,78.57 IC21.3 | v75.56,70.32 73.66,68.41 18.41,68.41 v12.06,74.77 | v44.45,145.25 45.08,144.62 56.51,144.62 v57.14,143.98 | v67.31,162.4 66.04,161.12 64.77,161.12 64.13,161.76 57.78,161.76 56.51,160.49 IC31.17 | v8.88,121.12 7.62,122.39 7.62,128.11 v43.17,128.11
DAR05  (via drill 0.61)
  Top 0.254: v86.36,30.32 90.8,34.76 90.8,74.13 89.53,75.4 IC21.2 | DAR4-7.6 46.35,140.17 49.52,143.34 49.52,157.31 50.79,158.59 IC31.15 50.16,160.49 v45.71,164.94 | v77.47,40.48 77.47,32.22 78.73,30.95 RS08.1 | v14.6,41.11 6.98,48.73 6.98,136.36 2.54,140.81 v2.54,153.5 | v203.19,218.28 207.64,213.83 IC39.3
  Bottom 0.254: v86.36,30.32 79.37,30.32 RS08.1 | 2.54,168.75 2.54,199.86 20.95,218.28 v203.19,218.28 | 2.54,168.75 17.78,168.75 20.32,166.21 31.11,166.21 31.75,166.84 31.75,168.75 41.27,168.75 41.9,168.11 41.9,164.94 v45.71,164.94 | v77.47,40.48 76.83,41.11 v14.6,41.11 | v2.54,153.5 1.27,154.78 1.27,168.75 2.54,168.75
DAR06  (via drill 0.61)
  Top 0.254: v80.01,74.13 79.37,73.49 79.37,55.08 73.66,49.37 73.66,33.49 RS08.6 | v47.62,142.71 46.98,143.34 46.98,157.31 45.71,158.59 IC31.13 | 69.84,220.81 v69.84,219.55 v69.84,162.4 | v65.4,159.22 64.77,158.59 v64.77,143.34 62.86,141.44 62.86,137 64.13,135.72 64.13,131.92 63.49,131.28 63.49,121.75 v66.04,119.21 | v85.09,110.32 85.72,109.69 85.72,76.67 88.26,74.13 IC21.1 | v81.28,111.59 80.01,112.86 v80.01,116.67 | v207,219.55 212.72,213.83 IC39.5
  Bottom 0.254: v80.01,74.13 86.99,74.13 87.62,73.49 IC21.1 | 53.97,141.44 52.7,142.71 v47.62,142.71 | 53.97,141.44 55.24,140.17 DAR4-7.2 | v69.84,162.4 66.67,159.22 v65.4,159.22 | v64.77,143.34 62.86,141.44 53.97,141.44 | v85.09,110.32 83.81,111.59 v81.28,111.59 | v80.01,116.67 79.37,117.31 74.93,117.31 73.02,119.21 v66.04,119.21 | v69.84,219.55 v207,219.55
DAR07  (via drill 0.61)
  Top 0.254: v53.34,143.34 53.34,140.81 DAR4-7.3 | v39.36,143.98 39.36,157.31 40.63,158.59 IC31.11 40.63,161.12 41.9,162.4 41.9,195.42 v41.27,196.05 | 137.79,51.27 137.79,29.68 139.06,28.41 IC1.9 | 137.79,51.27 139.06,52.54 IC2.9 | 137.79,76.67 139.06,77.94 IC3.9 | 137.79,76.67 137.79,51.27 | 137.79,76.67 137.79,102.07 139.06,103.34 IC4.9 140.33,104.61 141.6,105.88 141.6,217 100.33,217 v81.91,198.59 | v222.25,79.84 222.25,109.69 222.88,110.32 224.15,110.32 225.42,111.59 225.42,193.51 225.42,196.05 241.3,211.93 IC43.1 | v78.73,27.78 78.73,28.41 76.83,30.32 RS08.3
  Bottom 0.254: v53.34,143.34 52.7,143.98 v39.36,143.98 | v222.25,79.84 220.97,78.57 140.97,78.57 IC3.9 | v78.73,27.78 80.01,26.51 123.19,26.51 125.73,29.05 137.16,29.05 138.43,27.78 IC1.9 | v41.27,196.05 43.17,197.96 81.28,197.96 v81.91,198.59
DAR08  (via drill 0.61)
  Top 0.254: v72.39,161.76 72.39,145.89 73.02,145.25 73.02,141.44 73.66,140.81 DAR8-11.7 | 141.6,48.73 141.6,27.14 140.33,25.87 IC1.10 | 141.6,48.73 140.33,50 IC2.10 | 141.6,74.13 140.33,75.4 IC3.10 | 141.6,74.13 141.6,48.73 | 141.6,74.13 141.6,99.53 140.33,100.8 IC4.10 140.33,102.07 142.24,103.97 142.24,155.41 | v142.87,172.56 142.24,171.92 142.24,155.41 | v76.2,36.66 76.2,33.49 RS08.4 | v86.36,155.41 86.36,158.59 IC24.17 | v142.87,155.41 142.24,155.41 | v250.19,182.08 250.19,215.1 248.28,215.1 247.01,213.83 IC43.3
  Bottom 0.254: v72.39,161.76 84.45,161.76 85.72,160.49 IC24.17 | v250.19,182.08 247.65,179.54 149.86,179.54 v142.87,172.56 | v76.2,36.66 123.19,36.66 126.36,33.49 144.14,33.49 145.41,32.22 145.41,25.87 140.33,25.87 IC1.10 | v86.36,155.41 86.99,154.78 97.15,154.78 98.42,156.05 129.53,156.05 130.17,155.41 v142.87,155.41
DAR09  (via drill 0.61)
  Top 0.254: IC1.11 140.33,23.33 142.87,25.87 v142.87,46.83 v142.87,70.32 v142.87,96.99 | v81.28,137 81.28,136.36 79.37,136.36 76.83,138.9 DAR8-11.6 | v98.42,142.08 98.42,153.5 99.06,154.14 v99.06,163.03 | v82.55,163.03 81.28,161.76 81.28,161.12 IC24.15 | v102.87,163.03 v102.87,215.74 | v146.68,102.7 147.31,103.34 147.31,205.58 147.95,206.21 147.95,210.02 | 147.95,210.02 147.95,211.93 v144.78,215.1 | v251.46,210.02 251.46,211.93 IC43.5 | 147.95,210.02 v147.31,210.02
  Bottom 0.254: v142.87,46.83 141.6,48.09 140.97,48.09 IC2.11 | v142.87,70.32 140.33,72.86 IC3.11 | 141.6,98.26 v142.87,96.99 | 141.6,98.26 140.97,98.89 IC4.11 | RS08.5 74.29,30.32 75.56,31.59 99.69,31.59 102.23,29.05 124.45,29.05 125.09,29.68 140.33,29.68 141.6,28.41 141.6,26.51 138.43,26.51 137.79,25.87 137.79,23.33 139.06,23.33 IC1.11 | v81.28,137 81.91,137.63 93.98,137.63 v98.42,142.08 | v82.55,163.03 v99.06,163.03 v102.87,163.03 | v102.87,215.74 144.78,215.74 v144.78,215.1 | 141.6,98.26 146.05,102.7 v146.68,102.7 | v147.31,210.02 v251.46,210.02
DAR10  (via drill 0.61)
  Top 0.254: v78.73,143.34 77.47,142.08 74.93,142.08 74.93,157.31 | 74.93,157.31 76.2,158.59 IC24.13 | v90.17,217 73.02,199.86 73.02,185.25 74.93,183.35 74.93,157.31 | v82.55,7.46 v82.55,34.12
  Bottom 0.254: v78.73,143.34 82.55,143.34 85.72,140.17 DAR8-11.2 | v90.17,217 102.87,217 103.5,216.37 176.53,216.37 176.53,211.93 177.16,211.29 277.49,211.29 278.76,212.56 IC45.1 280.03,212.56 281.3,211.29 311.78,211.29 311.78,102.7 216.53,7.46 v82.55,7.46 | v82.55,34.12 70.48,34.12 69.21,32.86 RS08.10
DAR11  (via drill 0.61)
  Top 0.254: IC24.11 71.12,158.59 69.21,156.68 v69.21,142.08 69.84,141.44 69.84,110.32 72.39,107.78 72.39,50.63 69.84,48.09 69.84,32.22 71.12,30.95 RS08.7 71.12,29.68 71.12,27.78 72.39,26.51 72.39,21.43 v74.29,19.52 | 285.75,147.79 262.88,124.93 262.88,90.64 v181.61,9.36 | 285.75,147.79 290.82,152.87 | 285.75,147.79 285.75,210.66 284.48,211.93 IC45.3
  Bottom 0.254: v69.21,142.08 81.28,142.08 83.18,140.17 DAR8-11.3 | v181.61,9.36 180.97,8.73 125.73,8.73 120.65,13.81 114.3,13.81 108.58,19.52 v74.29,19.52
DATA00\
  Top 0.254: IC34.12 27.94,21.43 29.21,20.16 29.21,9.36 30.48,8.09 C35L.2
DATA01\
  Top 0.254: IC34.14 33.02,21.43 32.38,20.79 32.38,16.98 31.75,16.35 31.75,9.36 33.02,8.09 C35L.4
DATA02\
  Top 0.254: IC34.16 38.09,21.43 38.09,17.62 36.82,16.35 36.82,9.36 35.55,8.09 C35L.6
DATA03\
  Top 0.254: IC34.18 43.17,21.43 42.54,20.79 42.54,16.98 41.9,16.35 41.9,13.17 39.36,10.63 39.36,9.36 38.09,8.09 C35L.8
DATA04\  (via drill 0.61)
  Top 0.254: v72.39,8.73 72.39,12.54 73.66,13.81 IC26.3
  Bottom 0.254: v72.39,8.73 67.94,8.73 67.31,8.09 67.31,6.18 42.54,6.18 41.27,7.46 C35L.10
DATA05\  (via drill 0.61)
  Top 0.254: v67.31,4.92 67.31,12.54 68.58,13.81 IC26.5
  Bottom 0.254: v67.31,4.92 66.04,3.65 42.54,3.65 39.36,6.82 39.36,8.73 41.27,8.73 42.54,7.46 C35L.12
DATA06\
  Top 0.254: IC26.7 63.49,13.81 62.22,12.54 62.22,6.82 59.05,3.65 45.71,3.65 45.71,6.82 C35L.14
DATA07\  (via drill 0.61)
  Top 0.254: v50.79,14.44 49.52,13.17 49.52,9.36 48.25,8.09 C35L.16
  Bottom 0.254: v50.79,14.44 53.34,16.98 56.51,16.98 57.78,15.71 IC26.9
DATA08\  (via drill 0.61)
  Top 0.254: v58.41,17.62 58.41,21.43 IC26.12 | v52.7,17.62 52.06,16.98 52.06,9.36 50.79,8.09 C35L.18
  Bottom 0.254: v52.7,17.62 v58.41,17.62
DATA09\  (via drill 0.61)
  Top 0.254: v57.14,20.79 57.14,9.36 55.88,8.09 C35L.22
  Bottom 0.254: v57.14,20.79 61.59,20.79 62.86,22.06 IC26.14
DATA10\  (via drill 0.61)
  Top 0.254: v62.22,24.6 62.22,13.81 59.68,11.27 59.68,9.36 58.41,8.09 C35L.24
  Bottom 0.254: v62.22,24.6 66.67,24.6 67.94,23.33 IC26.16
DATA11\  (via drill 0.61)
  Top 0.254: v64.77,8.73 v64.77,20.79
  Bottom 0.254: v64.77,20.79 71.75,20.79 73.02,22.06 IC26.18 | v64.77,8.73 62.86,8.73 61.59,7.46 C35L.26
DATA_IN  (via drill 0.61)
  Top 0.254: v85.09,116.67 v85.09,111.59 | v100.96,116.67 102.23,117.94 102.23,124.93 102.87,125.56 106.04,125.56 v106.04,139.53 | v88.9,143.34 87.62,144.62 87.62,148.43 88.26,149.06 v90.17,149.06 | v107.31,157.31 v107.31,150.97 | v92.07,156.68 92.7,157.31 92.7,178.27 v91.44,179.54
  Bottom 0.254: v85.09,111.59 87.62,111.59 IC22.6 | v100.96,116.67 v85.09,116.67 | v106.04,139.53 102.23,143.34 v88.9,143.34 | v90.17,149.06 90.8,149.7 101.59,149.7 102.87,150.97 v107.31,150.97 | v107.31,157.31 106.04,158.59 102.23,158.59 100.33,156.68 v92.07,156.68 | v91.44,179.54 90.8,178.91 65.4,178.91 64.13,180.18 C36L.30
DCXA\
  Top 0.254: IC16.12 111.12,104.61 109.85,105.88 109.85,152.87 111.12,154.14 IC18.10 111.12,155.41 111.12,156.68 IC18.9
DIMA\  (via drill 0.61)
  Top 0.254: IC30.1 66.04,189.06 64.77,190.34 64.77,192.88 63.49,194.15 IC30.19 63.49,196.69 63.49,210.66 v66.04,213.2 | v107.95,139.53 v107.95,135.72 | v122.55,145.89 121.92,146.52 121.92,187.8 115.56,194.15 115.56,201.13 v104.14,212.56
  Bottom 0.254: IC37.1 36.19,187.16 37.46,185.89 64.13,185.89 65.4,187.16 IC30.1 | v107.95,135.72 111.12,132.55 IC17.11 | v107.95,139.53 111.76,143.34 115.56,143.34 118.11,145.89 v122.55,145.89 | v104.14,212.56 100.33,212.56 99.69,213.2 v66.04,213.2
DIML\  (via drill 0.61)
  Top 0.254: v81.28,181.45 82.55,182.72 82.55,192.88 81.28,194.15 FIELD.11 | v143.5,127.47 144.14,128.11 v144.14,180.81
  Bottom 0.254: INTENB.11 23.49,178.27 26.67,181.45 v81.28,181.45 143.5,181.45 v144.14,180.81 | v143.5,127.47 114.93,127.47 113.03,129.38 IC17.12
DIO00  (via drill 0.61)
  Top 0.254: IC34.8 30.48,16.35 31.75,17.62 v31.75,31.59 31.75,44.29 24.12,51.91 24.12,56.98 | 24.12,56.98 24.12,76.03 25.39,77.3 IC35.12 | IC13.12 111.12,36.03 109.85,37.3 109.85,53.81 111.12,55.08 IC14.12 | v154.3,55.08 168.91,69.68 168.91,93.81 165.09,97.62 IC33.1 | v29.21,56.98 24.12,56.98
  Bottom 0.254: v31.75,31.59 33.65,31.59 34.92,32.86 RS08.36 | v154.3,55.08 112.39,55.08 IC14.12 110.48,55.72 109.22,56.98 v29.21,56.98
DIO01  (via drill 0.61)
  Top 0.254: IC34.6 35.55,16.35 34.28,17.62 34.28,28.41 33.02,29.68 RS08.37 | v33.02,39.84 33.02,44.29 31.75,45.55 31.75,76.03 30.48,77.3 IC35.14 | IC13.11 112.39,38.57 113.66,39.84 113.66,56.35 112.39,57.62 IC14.11 | v161.92,96.99 154.3,89.37 v154.3,72.86
  Bottom 0.254: v33.02,39.84 18.41,39.84 17.14,38.57 | 17.14,38.57 17.14,29.05 31.11,29.05 32.38,30.32 RS08.37 | v161.92,96.99 168.27,96.99 169.54,98.26 IC33.3 | v154.3,72.86 140.33,58.89 112.39,58.89 IC14.11 | 17.14,38.57 15.87,39.84 14.6,39.84 13.33,41.11 13.33,42.38 47.62,42.38 48.25,41.74 116.2,41.74 117.47,40.48 117.47,38.57 112.39,38.57 IC13.11
DIO02  (via drill 0.61)
  Top 0.254: v36.82,20.16 36.82,28.41 35.55,29.68 RS08.35 35.55,30.95 34.28,32.22 v34.28,58.26 34.28,76.03 35.55,77.3 IC35.16 | v147.95,100.8 v147.95,65.24
  Bottom 0.254: v36.82,20.16 40.63,16.35 IC34.4 | IC13.10 110.48,40.48 109.22,39.2 66.04,39.2 65.4,39.84 43.17,39.84 36.82,33.49 36.82,30.95 35.55,30.95 RS08.35 | 107.95,59.52 41.9,59.52 40.63,58.26 v34.28,58.26 | 107.95,59.52 109.22,59.52 110.48,60.8 IC14.10 | v147.95,100.8 173.35,100.8 174.62,99.53 IC33.5 | v147.95,65.24 140.97,58.26 114.3,58.26 113.03,56.98 110.48,56.98 107.95,59.52
DIO03  (via drill 0.61)
  Top 0.254: v40.63,20.16 39.36,21.43 39.36,28.41 | 39.36,28.41 38.09,29.68 RS08.33 | 39.36,59.52 39.36,28.41 | 39.36,59.52 39.36,76.03 40.63,77.3 IC35.18 | v108.58,45.55 109.22,46.19 109.22,60.8 111.12,62.7 IC14.9 | v193.03,55.08 193.03,87.46 203.19,97.62 IC42.1 | v40.63,59.52 39.36,59.52
  Bottom 0.254: v40.63,20.16 45.08,15.71 IC34.2 | 110.48,44.29 109.22,45.55 v108.58,45.55 | 110.48,44.29 111.12,43.65 IC13.9 | v193.03,55.08 179.7,41.74 137.79,41.74 133.98,45.55 133.98,46.83 130.81,46.83 128.27,49.37 125.73,49.37 120.65,44.29 110.48,44.29 | v40.63,59.52 41.27,60.16 100.96,60.16 102.87,62.06 109.22,62.06 110.48,63.34 IC14.9
DIO04  (via drill 0.61)
  Top 0.254: v56.51,25.23 52.06,29.68 52.06,30.95 50.79,32.22 RS08.24 | v68.58,74.13 68.58,72.22 IC28.3 68.58,69.68 68.58,35.4 v67.31,34.12 | v207,79.84 207,96.35 208.28,97.62 IC42.3
  Bottom 0.254: v56.51,25.23 57.14,25.87 67.94,25.87 70.48,23.33 IC26.17 | v68.58,74.13 69.21,73.49 79.37,73.49 80.64,72.22 101.59,72.22 102.87,73.49 IC15.2 105.41,73.49 106.68,74.77 113.03,74.77 118.11,79.84 v207,79.84 | v67.31,34.12 52.7,34.12 51.43,32.86 RS08.24
DIO05  (via drill 0.61)
  Top 0.254: v64.77,35.4 64.77,25.23 66.04,23.96 IC26.15 | v109.85,82.38 109.22,81.75 v109.22,73.49 | v61.59,36.03 61.59,67.78 63.49,69.68 IC28.5
  Bottom 0.254: v64.77,35.4 64.13,34.76 61.59,34.76 | 61.59,34.76 50.79,34.76 48.89,32.86 RS08.26 | IC28.5 64.13,71.59 65.4,72.86 78.73,72.86 80.64,70.95 102.87,70.95 IC15.1 105.41,70.95 106.68,72.22 107.95,72.22 v109.22,73.49 | v109.85,82.38 113.03,82.38 113.66,83.02 174.62,83.02 185.41,93.81 208.28,93.81 212.72,98.26 IC42.5 | v61.59,36.03 61.59,34.76
DIO06  (via drill 0.61)
  Top 0.254: v54.6,29.05 59.68,29.05 60.95,27.78 60.95,23.96 IC26.13 | v59.68,36.66 v59.68,66.51 59.68,68.41 58.41,69.68 IC28.7 | v238.12,102.07 240.66,99.53 IC44.1 | v125.09,112.86 123.82,111.59 123.82,79.21 v124.45,78.57
  Bottom 0.254: v54.6,29.05 47.62,29.05 46.98,29.68 46.98,32.22 45.71,32.22 RS08.28 46.35,32.86 48.89,35.4 58.41,35.4 v59.68,36.66 | 121.92,76.03 125.09,72.86 125.09,70.32 123.82,70.32 120.65,67.14 60.32,67.14 v59.68,66.51 | 121.92,76.03 120.65,77.3 116.84,77.3 113.03,73.49 IC15.13 | v238.12,102.07 152.4,102.07 141.6,112.86 v125.09,112.86 | v124.45,78.57 121.92,76.03
DIO07  (via drill 0.61)
  Top 0.254: IC26.11 55.24,23.33 49.52,23.33 49.52,25.23 47.62,27.14 47.62,29.05 46.98,29.68 46.98,30.95 46.35,31.59 43.17,31.59 43.17,32.22 RS08.30 43.17,33.49 48.25,38.57 48.25,60.8 52.7,65.24 52.7,69.05 53.34,69.68 IC28.9 53.34,72.22 v55.24,74.13 | v114.3,81.11 114.93,80.48 v114.93,79.21
  Bottom 0.254: v55.24,74.13 56.51,75.4 80.01,75.4 80.64,74.77 97.79,74.77 100.33,77.3 109.22,77.3 110.48,76.03 IC15.12 112.39,76.67 v114.93,79.21 | v114.3,81.11 115.56,82.38 175.25,82.38 186.05,93.18 208.91,93.18 212.72,96.99 244.47,96.99 245.74,98.26 IC44.3
DIO08  (via drill 0.61)
  Top 0.254: v59.68,27.78 59.68,17.62 60.95,16.35 IC26.8 | v48.25,78.57 48.25,74.77 46.35,72.86 46.98,72.22 46.98,69.68 46.35,69.05 46.35,39.2 40.63,33.49 RS08.32
  Bottom 0.254: v59.68,27.78 43.81,27.78 41.9,29.68 41.9,32.22 40.63,32.22 RS08.32 | IC44.5 250.82,98.26 245.11,92.54 245.11,81.75 116.2,81.75 113.03,78.57 IC15.11 110.48,78.57 109.22,79.84 87.62,79.84 86.99,80.48 55.24,80.48 53.97,79.21 IC28.12 52.7,79.21 51.43,80.48 50.16,80.48 v48.25,78.57
DIO09  (via drill 0.61)
  Top 0.254: v45.71,18.89 44.45,20.16 44.45,28.41 43.17,29.68 RS08.29 42.54,30.32 41.9,30.95 41.9,33.49 46.98,38.57 46.98,60.8 52.06,65.88 52.06,75.4 55.24,75.4 56.51,74.13 54.6,72.22 54.6,69.05 56.51,69.05 | 56.51,69.05 57.14,69.68 57.14,72.22 57.78,72.86 57.78,76.67 58.41,77.3 IC28.14 | v114.3,65.88 114.3,78.57 112.39,80.48 IC15.10 | v58.41,64.6 56.51,66.51 56.51,69.05 | v236.85,56.35 278.76,98.26 IC46.1 | v128.27,56.35 122.55,62.06 v122.55,62.7
  Bottom 0.254: v45.71,18.89 62.22,18.89 65.4,15.71 IC26.6 | 113.03,64.6 v114.3,65.88 | 113.03,64.6 v58.41,64.6 | v236.85,56.35 v128.27,56.35 | v122.55,62.7 120.65,64.6 113.03,64.6
DIO10  (via drill 0.61)
  Top 0.254: v71.12,11.9 71.12,13.81 IC26.4 | v46.98,12.54 46.98,28.41 45.71,29.68 RS08.27 | 64.77,79.84 66.04,81.11 v66.04,81.75 | 64.77,79.84 64.13,79.21 IC28.16 | v116.2,80.48 113.03,83.65 IC15.9 | v62.86,37.94 62.86,67.78 64.77,69.68 64.77,79.84
  Bottom 0.254: v71.12,11.9 70.48,12.54 v46.98,12.54 | v66.04,81.75 86.99,81.75 87.62,82.38 108.58,82.38 109.85,83.65 110.48,83.65 IC15.9 | v116.2,80.48 116.84,81.11 247.65,81.11 247.65,92.54 248.28,93.18 278.76,93.18 283.84,98.26 IC46.3 | v62.86,37.94 59.68,37.94 59.05,37.3 44.45,37.3 44.45,32.22 45.71,30.95 RS08.27
DIO11  (via drill 0.61)
  Top 0.254: 49.52,26.51 48.25,27.78 48.25,29.68 RS08.25 | 49.52,26.51 v50.79,25.23 | v69.84,54.45 69.84,76.03 68.58,77.3 IC28.18 | v52.06,51.91 49.52,49.37 49.52,26.51 | v107.31,18.25 116.2,27.14 116.2,45.55 115.56,46.19 115.56,56.35 117.47,58.26 117.47,80.48 112.39,85.56 IC15.8 | v296.54,90.64 296.54,91.91 290.19,98.26 IC46.5
  Bottom 0.254: 74.29,16.98 73.02,18.25 64.13,18.25 62.86,19.52 56.51,19.52 v50.79,25.23 | 74.29,16.98 75.56,15.71 IC26.2 | v69.84,54.45 67.31,51.91 v52.06,51.91 | 74.29,16.98 106.04,16.98 v107.31,18.25 108.58,18.25 118.74,8.09 213.99,8.09 v296.54,90.64
DIOEVEN  (via drill 0.61)
  Top 0.254: v97.15,33.49 v100.33,33.49 | v30.48,50 30.48,64.6 25.39,69.68 IC35.9 | v37.46,45.55 38.09,44.92 38.09,33.49 RS08.34
  Bottom 0.254: v100.33,33.49 100.96,34.12 109.22,34.12 110.48,32.86 IC13.13 | v97.15,33.49 94.61,36.03 76.83,36.03 76.2,35.4 68.58,35.4 64.77,39.2 45.08,39.2 38.73,32.86 RS08.34 | v30.48,50 34.92,45.55 v37.46,45.55
DMA00  (via drill 0.61)
  Top 0.254: v22.22,207.48 8.25,193.51 v8.25,150.33 8.25,123.02 v8.88,122.39 7.62,121.12 7.62,58.26 v12.06,53.81 | v74.93,49.37 v74.93,27.78 | v252.72,207.48 252.72,215.1 287.65,215.1 288.92,213.83 IC45.5
  Bottom 0.254: v8.88,122.39 10.79,122.39 12.06,123.66 DMA0-3.7 | v8.25,150.33 13.33,150.33 14.6,151.6 IC38.8 | v22.22,207.48 104.14,207.48 104.77,208.12 175.25,208.12 | v74.93,27.78 62.22,27.78 62.22,30.95 60.95,32.22 RS08.16 | v74.93,49.37 73.66,50.63 31.11,50.63 27.94,53.81 v12.06,53.81 | 175.25,208.12 177.16,206.21 IC27.9 | v252.72,207.48 252.09,208.12 175.25,208.12
DMA01  (via drill 0.61)
  Top 0.254: v72.39,204.31 72.39,218.28 170.18,218.28 173.99,214.47 173.99,208.12 172.72,206.84 IC27.11 | v25.39,197.96 24.12,196.69 24.12,183.99 24.76,183.35 24.76,182.08 24.12,181.45 20.95,181.45 20.95,161.76 21.59,161.12 21.59,156.68 20.32,155.41 20.32,153.5 IC38.6 20.32,150.97 21.59,149.7 21.59,138.27 16.51,133.19 16.51,126.83 15.23,125.56 DMA0-3.6 15.23,123.02 15.23,116.67 v14.6,116.04 | v55.88,53.18 55.88,33.49 RS08.20
  Bottom 0.254: v72.39,204.31 71.75,203.67 31.11,203.67 v25.39,197.96 | v55.88,53.18 53.97,55.08 6.34,55.08 6.34,112.86 11.42,112.86 v14.6,116.04
DMA02  (via drill 0.61)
